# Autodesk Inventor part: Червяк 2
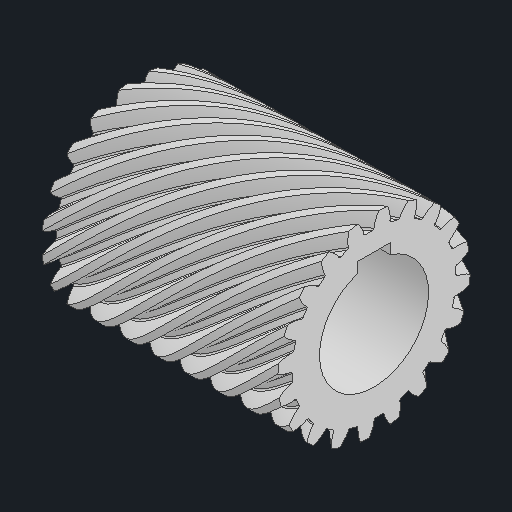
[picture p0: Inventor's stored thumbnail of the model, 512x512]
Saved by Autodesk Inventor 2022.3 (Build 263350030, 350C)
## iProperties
Created: 2020-09
Part Number: Червяк 2
Material: Типовые
Document SubType Name: Modeling
Designer: Карташов
Density: 1 g/cm^3
Appearance: По умолчанию
Title: D:\мои документы\Ирина\_WorldSkills\2020_09 ФНЧ\Module A\GIVEN\Червяк 2.stp
Author: Дом
Sending System: Autodesk Inventor 2021
Preprocessor: ST-DEVELOPER v18.1
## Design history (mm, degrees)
feature "Твердое тело2"
node "Твердое тело1"
